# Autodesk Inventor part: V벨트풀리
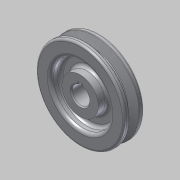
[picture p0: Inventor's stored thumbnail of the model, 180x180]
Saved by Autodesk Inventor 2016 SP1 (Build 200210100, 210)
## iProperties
Created: 2018-11
Part Number: V벨트풀리
Material: 알루미늄 6061
Document SubType Name: Modeling
Designer: mduedu
Density: 1 g/cm^3
Appearance: 알루미늄 - 평지
Author: mduedu
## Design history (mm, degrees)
sketch "스케치1"
  geometry: L1 (-9.5, 0)-(9.5, 0); L2 (9.5, 0)-(9.5, 42.7); L3 (9.5, 42.7)-(-9.5, 42.7); L4 (-9.5, 42.7)-(-9.5, 0); L5 (-4.877, 42.7)-(-1.953, 33.7); L6 (-1.953, 33.7)-(1.953, 33.7); L7 (1.953, 33.7)-(4.877, 42.7); L8 (0, 0)-(0, 42.7); L9 (-9.5, 40)-(9.5, 40); 3 further points
  constraints: 18 end point, 8 point on line, 3 perpendicular, 2 midpoint, 2 parallel, 1 coincident, 1 horizontal, 1 other
  dimensions: "d0" = 85.4 diameter of L3 L1; "d2" = 19 distance of L2.end L3.end; "d3" = 80 diameter of L9 L1; "d4" = 36 deg angle of L7 L5; "d5" = 6.3 distance between parallel lines of L6 L9; "d6" = 8 distance of point (4, 40) point (-4, 40)
revolve "회전1" sketch "스케치1" stored, may be unused: angle "d7" = 90 deg
sketch "스케치2"
  geometry: L1 (-2.5, 8.124)-(2.5, 8.124); L2 (2.5, 8.124)-(2.5, 10.8); L3 (2.5, 10.8)-(-2.5, 10.8); L4 (-2.5, 10.8)-(-2.5, 8.124); A1 r 8.5 centre (0, 0) between (-2.5, 8.124) and (2.5, 8.124); 1 further point
  constraints: 8 end point, 2 parallel, 2 point on circle, 1 centre point, 1 coincident, 1 horizontal, 1 perpendicular
  dimensions: "d8" = 17 diameter of A1; "d10" = 19.3 dimension on A1 L3; "d11" = 5 distance of L2.end L3.end
extrude "돌출1" cut sketch "스케치2" stored distance "d12" = 10; taper "d13" = 0 deg
chamfer "모따기1" distance "d14" = 1; stored, may be unused: second distance "d15" = 2, angle "d16" = 45 deg
fillet "모깎기1" dims "d17" = 1, "d18" = 0.5, "d19" = 2
sketch "스케치3"
  geometry: C1 r 17.5 at (0, 0); C2 r 28.5 at (0, 0); 1 further point
  constraints: 2 centre point, 2 coincident
  dimensions: "d20" = 35 diameter of C1; "d23" = 57 diameter of C2
extrude "돌출2" cut sketch "스케치3" distance "d24" = 9.5; taper "d25" = 0 deg
fillet "모깎기2" dims "d26" = 3
node "솔리드1"
